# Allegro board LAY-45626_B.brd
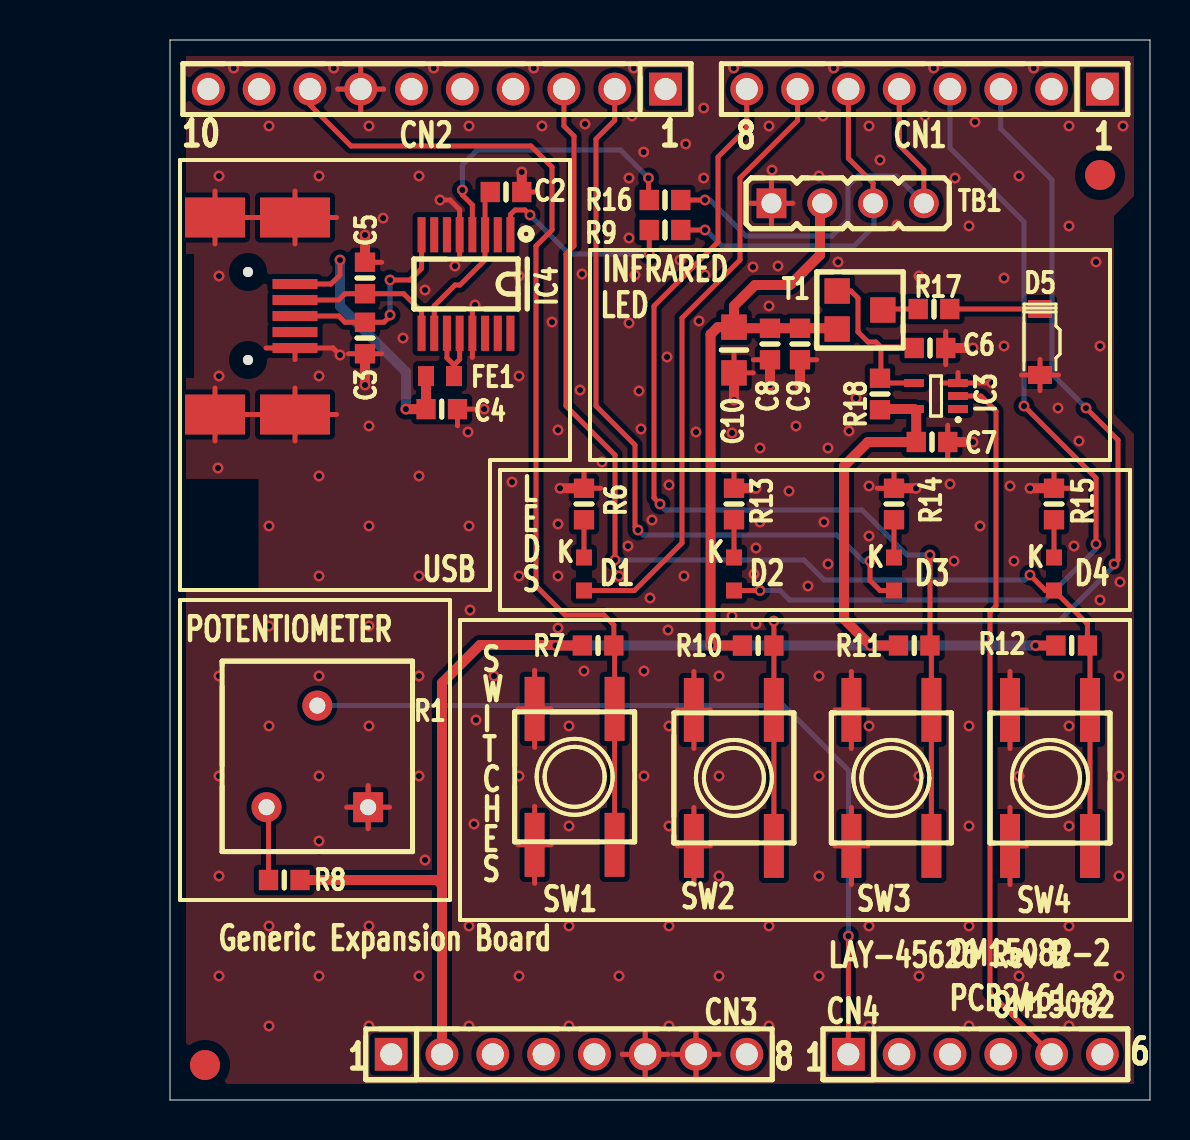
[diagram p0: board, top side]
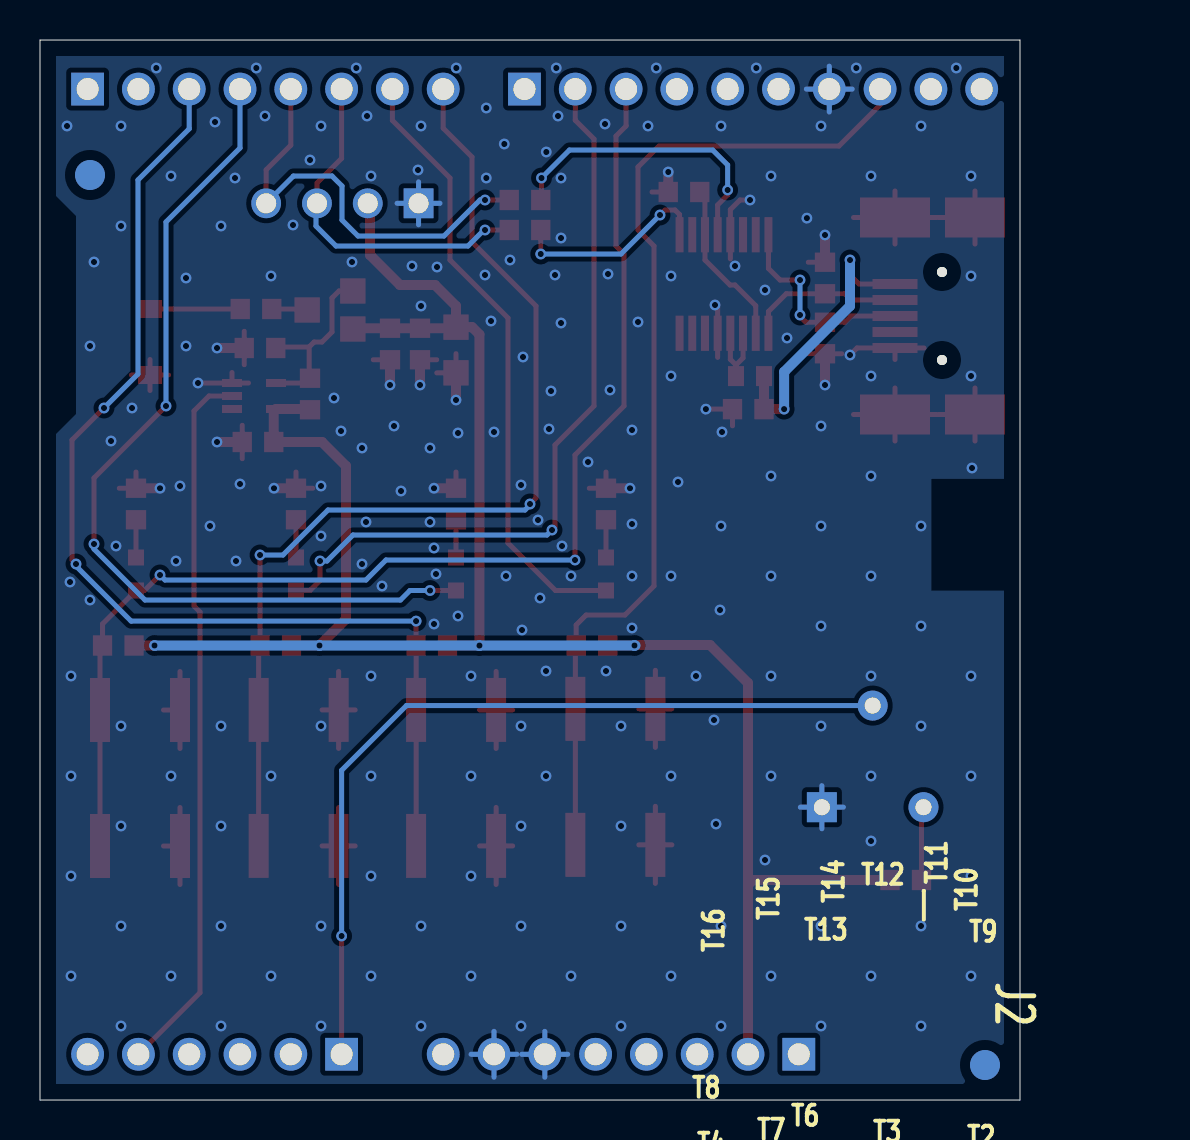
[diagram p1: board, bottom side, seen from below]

Outline 49 x 53 mm; copper layers: TOP, BOTTOM. Coordinates in mm from the lower left corner of the outline.
Outline path: 0,53 49,53 49,0 0,0 0,53

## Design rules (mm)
constraint set DEFAULT: min track width 0.15
net group ALIM: nets 3V3OUT N12889 VCC VCC3.3V VCC5V VCCUSB VIN
net group DEFAUT: nets ADC0 IR_BLASTER N01844 N09961 N10143 N10285 N10430 N15485 N15494 N16219 N16257 N23077 N262631 PIO_3 PIO_4 PIO_6 PIO_7 PIO_15 PIO_16 PIO_19 RSTN USART1_RXD USART1_TXD

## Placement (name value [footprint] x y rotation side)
1  BUBBLE-01  [BUBBLE_DIAM8]  -6.5 26.7 0 top
C2  100nF  [C0603]  16.8 45.4 0 top
C3  47pF  [C0603]  9.75 38.1 270 top
C4  10nF  [C0603]  13.59 34.54 0 top
C5  47pF  [C0603]  9.75 41.1 90 top
C6  150pF  [C0603]  38 37.6 0 top
C7  100nF  [C0603]  38.1 32.9 0 top
C8  100nF  [C0603]  30 37.8 270 top
C9  27pF  [C0603]  31.5 37.8 270 top
C10  47uF  [C0805]  28.2 37.5 270 top
CN1  -  [ESQ-108-14-L-S]  46.62 50.55 0 top
CN2  -  [ESQ-110-14-L-S]  24.78 50.55 0 top
CN3  -  [ESQ-108-14-L-S]  11.06 2.29 180 top
CN4  -  [ESQ-106-14-L-S]  33.92 2.29 180 top
D1  RED  [LED_0603_A_K]  20.7 26.3 270 top
D2  RED  [LED_0603_A_K]  28.2 26.3 270 top
D3  RED  [LED_0603_A_K]  36.2 26.3 270 top
D4  RED  [LED_0603_A_K]  44.2 26.3 270 top
D5  VSMB2948SL  [LED_VSMB2948SL]  43.5 37.9 90 top
FE1  470R  [BLM18]  13.5 36.2 0 top
IC3  74LVC1G07  [SOT353_065]  38.3 35.2 180 top
IC4  FT230XS  [JEDEC_MO137_AB_SSOP16]  14.8 40.8 180 top
J2  -  [USB_MINI-B]  0 39.2 0 top
NOREF  -  []  6.9 5.2 0 top
NOREF#2  -  []  -76.6 -194.1 0 top
NOREF#3  -  []  1 30.8 270 top
NOREF#4  -  []  16 0 90 top
NOREF#5  -  [unnamed#2]  46.5 46.25 0 top
NOREF#6  -  []  1.92 50.55 90 top
NOREF#7  -  []  0 53 0 top
NOREF#8  -  []  0 53 0 top
NOREF#9  -  []  13.15 -115.65 0 top
NOREF#10  -  [unnamed#2]  1.75 1.75 0 top
NOREF#11  -  []  0 0 90 top
NOREF#12  -  [unnamed#2]  1.75 1.75 180 bottom
NOREF#13  -  [unnamed#2]  46.5 46.25 180 bottom
R1  50K  [TRIM_63M_T607]  7.37 17.18 180 top
R6  680R  [R0603]  20.7 29.8 90 top
R7  2K20  [R0603]  21.4 22.73 0 top
R8  33K0  [R0603]  5.71 11 180 top
R9  0R  [R0603]  24.75 43.5 180 top
R10  2K20  [R0603]  29.41 22.72 0 top
R11  2K20  [R0603]  37.21 22.73 0 top
R12  2K20  [R0603]  45.09 22.73 0 top
R13  680R  [R0603]  28.2 29.8 90 top
R14  680R  [R0603]  36.2 29.8 90 top
R15  680R  [R0603]  44.2 29.8 90 top
R16  0R  [R0603]  24.75 45 180 top
R17  68R  [R0603]  38.2 39.55 0 top
R18  100K  [R0603]  35.5 35.3 90 top
SW1  EVQ-Q2P03W  [BP_EVQQ2]  20.23 16.16 270 top
SW2  EVQ-Q2P03W  [BP_EVQQ2]  28.19 16.1 270 top
SW3  EVQ-Q2P03W  [BP_EVQQ2]  36.07 16.1 270 top
SW4  EVQ-Q2P03W  [BP_EVQQ2]  44 16.1 270 top
T1  BSS84  [SOT23_1G_2S_3D]  34.5 39.5 270 top
TB1  NC  [BAR_1X4_MD]  30.07 44.83 0 top

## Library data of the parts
1 = BUBBLE: alternate symbols: (BUBBLE_DIAM4)
C2 C4 C7 C8 = CAPA: Tolerance: 10%; User Part Number: PARTNUM; alternate symbols: (0603C); tolerance: 10%
C3 C5 C6 = CAPA: Tolerance: 5%; User Part Number: PARTNUM; alternate symbols: (0603C); tolerance: 5%
C9 = CAPA: Tolerance: 5%; User Part Number: PARTNUM; tolerance: 5%
C10 = CAPA: User Part Number: PARTNUM; Tolerance: 20%; alternate symbols: (0805C); tolerance: 20%
CN1 CN3 = HEADER_8P: Tolerance: TOL; User Part Number: PAR
CN2 = HEADER_10P: Tolerance: TOL; User Part Number: PAR
CN4 = HEADER_6P: Tolerance: TOL; User Part Number: PAR
D1-D4 = LED
D5 = LED_VSMB2948G
FE1 = FERRITE_2: Tolerance: TOLERANCE; User Part Number: PARTNUM
IC3 = 74LVC1G07
IC4 = FT230XS: User Part Number: PARTNUM; Tolerance: TOLERANCE
J2 = USB_MINI-B
R1 = POT: User Part Number: PARTNUM; Tolerance: TOLERANCE
R6-R8 R10-R15 R17 = RES: User Part Number: PARTNUM; Tolerance: 1%; alternate symbols: (0603R); tolerance: 1%
R9 R16 = RES: User Part Number: PARTNUM; Tolerance: 1%; tolerance: 1%
R18 = RES: User Part Number: PARTNUM; Tolerance: 5%; tolerance: 5%
SW1-SW4 = BP_EVQQ2: User Part Number: PARTNUM; Tolerance: TOLERANCE
T1 = MOSFET_G1_S2_D3: User Part Number: PARTNUM; Tolerance: TOLERANCE
TB1 = bar_1x4_MD: Tolerance: TOLERANCE; User Part Number: PARTNUM

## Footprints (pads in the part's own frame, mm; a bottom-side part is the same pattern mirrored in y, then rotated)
BAR_1X4_MD
  rect 1.49x1.49 hole 1: 1(0,0)
  round 1.49 hole 1: 2(2.54,0) 3(5.08,0) 4(7.62,0)
BLM18
  rect 0.8x1 smd: 1(-0.7,0) 2(0.7,0)
BP_EVQQ2
  rect 3.2x1 smd: A(-3.4,-2) AP(3.4,-2) B(-3.4,2) BP(3.4,2)
BUBBLE_DIAM8
  round 0 smd: 1(0,0)
C0603
  rect 0.965x1.016 smd: 1(-0.787,0) 2(0.787,0)
C0805
  rect 1.27x1.27 smd: 1(-1.143,0) 2(1.143,0)
ESQ-106-14-L-S
  rect 1.64x1.64 hole 1.1: 1(0,0)
  round 1.64 hole 1.1: 2(-2.54,0) 3(-5.08,0) 4(-7.62,0) 5(-10.16,0) 6(-12.7,0)
ESQ-108-14-L-S
  rect 1.64x1.64 hole 1.1: 1(0,0)
  round 1.64 hole 1.1: 2(-2.54,0) 3(-5.08,0) 4(-7.62,0) 5(-10.16,0) 6(-12.7,0) 7(-15.24,0) 8(-17.78,0)
ESQ-110-14-L-S
  rect 1.64x1.64 hole 1.1: 1(0,0)
  round 1.64 hole 1.1: 2(-2.54,0) 3(-5.08,0) 4(-7.62,0) 5(-10.16,0) 6(-12.7,0) 7(-15.24,0) 8(-17.78,0) 9(-20.32,0) 10(-22.86,0)
JEDEC_MO137_AB_SSOP16
  rect 0.4x1.76 smd: 1(-2.223,-2.462) 2(-1.587,-2.462) 3(-0.953,-2.462) 4(-0.318,-2.462) 5(0.318,-2.462) 6(0.953,-2.462) 7(1.587,-2.462) 8(2.223,-2.462) 9(2.223,2.462) 10(1.587,2.462) 11(0.953,2.462) 12(0.318,2.462) 13(-0.318,2.462) 14(-0.953,2.462) 15(-1.587,2.462) 16(-2.223,2.462)
LED_0603_A_K
  rect 0.8x0.8 smd: A(0.825,0) K(-0.825,0)
LED_VSMB2948SL
  rect 0.9x1.2 smd: A(1.65,0) K(-1.65,0)
R0603
  rect 0.965x1.016 smd: 1(-0.787,0) 2(0.787,0)
SOT23_1G_2S_3D
  rect 1.27x1.27 smd: 1(-0.95,-1.143) 2(0.95,-1.143) 3(0,1.143)
SOT353_065
  rect 1x0.4 smd: 1(-1.1,0.65) 2(-1.1,0) 3(-1.1,-0.65) 4(1.1,-0.65) 5(1.1,0.65)
TRIM_63M_T607
  rect 1.5x1.5 hole 0.8: 1(-2.54,2.54)
  round 1.5 hole 0.8: 2(0,-2.54) 3(2.54,2.54)
unnamed#2
  round 1.5 smd: (0,0)
USB_MINI-B
  round 0.5 hole 0.9 unplated: (3.9,2.2) (3.9,-2.2)
  rect 2.25x0.5 smd: 1(6.25,1.6) 2(6.25,0.8) 3(6.25,0) 4(6.25,-0.8) 5(6.25,-1.6)
  rect 3.5x2 smd: A(6.25,4.925) C(6.25,-4.925)
  rect 3x2 smd: B(2.25,4.925) D(2.25,-4.925)

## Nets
3V3OUT: C2.1 IC4.3(VCCIO) IC4.10
GND: C2.2 C3.2 C4.2 C5.2 C6.2 C7.2 C8.2 C9.2 C10.2 CN2.7 CN3.6 CN3.7 D5.K IC3.3 IC4.5 IC4.13 J2.5 J2.A J2.B J2.C J2.D R1.1 R6.2 R13.2 R14.2 R15.2 SW1.A SW1.AP SW2.A SW2.AP SW3.A SW3.AP SW4.A SW4.AP TB1.1
VCC: C7.1 C8.1 C9.1 C10.1 CN3.2 IC3.5 R7.1 R8.1 R10.1 R11.1 R12.1 R18.1 T1.2(S) TB1.2
VCC3.3V: CN3.4
VCC5V: CN3.5
VCCUSB: FE1.2 IC4.11 IC4.12
VIN: CN3.8
ADC0: CN4.1 R1.2
IR_BLASTER: CN4.5 IC3.2
PIO_3: CN2.2 D3.A
PIO_4: CN2.3 D4.A R12.2 SW4.B SW4.BP
PIO_6: CN1.4 D2.A
PIO_7: CN1.8 R11.2 SW3.B SW3.BP
PIO_15: CN1.3 R10.2 SW2.B SW2.BP
PIO_16: CN1.7 D1.A
PIO_19: CN2.8 R7.2 SW1.B SW1.BP
RSTN: CN3.3
USART1_RXD: CN1.6 R9.1 TB1.3
USART1_TXD: CN1.5 R16.1 TB1.4
N01844: R1.3 R8.2
N09961: D1.K R6.1
N10143: D2.K R13.1
N10285: D3.K R14.1
N10430: D4.K R15.1
N12889: C4.1 FE1.1 J2.1(VCC)
N15485: C5.1 IC4.9 J2.2
N15494: C3.1 IC4.8 J2.3
N16219: IC4.1 R9.2
N16257: IC4.4 R16.2
N23077: C6.1 IC3.4(Y) R18.2 T1.1
N226982: R17.1 T1.3
N262631: D5.A R17.2

Pads without a net: 1 1; CN1 1 2; CN2 1 4 5 6 9 10; CN3 1; CN4 2 3 4 6; IC3 1; IC4 2 6 7 14 15 16; J2 4

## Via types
v1: diameter 0.54, hole 0.31, TOP to BOTTOM, 233 vias

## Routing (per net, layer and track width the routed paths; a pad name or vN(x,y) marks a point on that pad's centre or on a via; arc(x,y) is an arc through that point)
3V3OUT: length 8.4
  TOP w0.25: C2.1 15.75,45.14 IC4.3 15.75,43.26 15.75,42 14.5,40.75 14.25,40.75 13.21,39.71 IC4.10
GND: length 159.9
  TOP w0.25: 42,17.57 SW4.A ; SW4.A 42,21.43 ; SW4.A 42.83,19.5 ; 6.25,37.02 J2.5 ; J2.5 4.8,37.6 ; J2.5 8.15,37.6 v1(8.5,37.25) ; 21.53,30.59 R6.2 20.7,31.4 ; J2.B 2.25,45.45 ; J2.B 2.25,42.8 ; J2.B 4.08,44.13 ; D5.K 43.5,37.03 ; D5.K 43.5,35.47 ; D5.K 44.43,36.25 ; D5.K 42.57,36.25 ; SW1.A 19.06,19.56 ; SW1.A 18.23,21.48 ; SW1.A 18.23,17.63 ; SW1.A 17.41,19.56 ; SW4.AP 42.83,12.7 ; SW4.AP 42,14.63 ; SW4.AP 42,10.77 ; v1(15.25,39.75) 15.12,39.62 IC4.13 15.12,37.13 ; SW2.A 27.02,19.5 ; SW2.A 26.19,21.43 ; SW2.A 26.19,17.58 ; SW2.A 25.37,19.5 ; SW3.A 34.07,21.43 ; SW3.A 34.89,19.5 ; SW3.A 34.07,17.58 ; SW3.A 33.24,19.5 ; 29.17,37.01 C8.2 ; 38.89,32.07 C7.2 38.89,33.73 ; SW1.AP 19.06,12.76 ; SW1.AP 18.23,14.68 ; SW1.AP 18.23,10.83 ; SW1.AP 17.41,12.76 ; 25.37,12.7 SW2.AP ; SW2.AP 26.19,10.78 ; SW2.AP 27.02,12.7 ; SW2.AP 26.19,14.63 ; 29,44.83 TB1.1 ; TB1.1 31.14,44.83 ; TB1.1 30.07,43.76 ; TB1.1 30.07,45.9 ; v1(15.71,34.54) C4.2 14.37,33.71 ; C9.2 32.33,37.01 ; R13.2 28.2,31.4 ; 33.24,12.7 SW3.AP ; SW3.AP 34.07,10.78 ; SW3.AP 34.07,14.63 ; SW3.AP 34.89,12.7 ; 14.48,42.06 IC4.5 14.48,44.52 14,45 v1(13.5,45) ; J2.D 2.25,35.6 ; J2.D 4.08,34.27 ; J2.D 2.25,32.95 ; 9.91,13.56 R1.1 ; R1.1 9.91,15.72 ; R1.1 8.83,14.64 ; R1.1 10.98,14.64 ; 38.79,38.43 C6.2 38.79,36.77 ; 8.92,37.31 C3.2 10.58,37.31 ; 22.61,2.29 CN3.6 ; CN3.6 23.76,3.43 ; CN3.6 23.76,1.14 ; CN3.6 24.91,2.29 ; J2.A 8.33,44.13 ; J2.A 6.25,42.8 ; J2.A 6.25,45.45 ; J2.A 4.17,44.13 ; 45.03,30.59 R15.2 44.2,31.4 ; 35.37,30.59 R14.2 36.2,31.4 ; IC3.3 v1(41.1,35.85) ; IC3.3 39.4,36.38 ; IC3.3 38.57,35.85 ; J2.C 8.33,34.27 ; J2.C 6.25,35.6 ; J2.C 6.25,32.95 ; J2.C 4.17,34.27 ; CN2.7 10.68,50.55 ; CN2.7 9.54,51.69 ; CN2.7 8.39,50.55 ; CN2.7 9.54,49.4 ; 26.3,1.14 CN3.7 ; CN3.7 25.15,2.29 ; CN3.7 26.3,3.43 ; CN3.7 27.45,2.29 ; 29.16,36.36 C10.2 28.2,37.32 ; C2.2 18.4,45.4 ; C5.2 10.58,41.89
  TOP w0.5: C6.2 v1(40.15,37.6) ; v1(37.3,30.59) R14.2 ; v1(29.3,30.59) R13.2 ; C5.2 v1(9.75,43.25) ; v1(17.59,46.4) C2.2 ; C9.2 v1(31.5,35.75) ; C7.2 v1(40.15,32.9) ; C10.2 v1(28.2,35) ; C8.2 v1(30,35.75) ; v1(43,30.59) R15.2 ; v1(19.5,30.59) R6.2 ; C3.2 v1(9.75,35.75)
  BOTTOM w0.25: 9.54,49.4 CN2.7 ; CN2.7 8.39,50.55 ; CN2.7 9.54,51.69 ; CN2.7 10.68,50.55 ; 8.83,14.64 R1.1 ; R1.1 10.98,14.64 ; R1.1 9.91,13.56 ; R1.1 9.91,15.72 ; CN3.7 27.45,2.29 ; CN3.7 25.15,2.29 ; CN3.7 26.3,3.43 ; CN3.7 26.3,1.14 ; CN3.6 23.76,3.43 ; CN3.6 23.76,1.14 ; CN3.6 22.61,2.29 ; CN3.6 24.91,2.29 ; TB1.1 31.14,44.83 ; TB1.1 30.07,45.9 ; TB1.1 30.07,43.76 ; TB1.1 29,44.83
  vias: v1(2.4,31.6) v1(2.45,46.2) v1(2.45,41.2) v1(2.45,36.2) v1(2.45,21.2) v1(2.45,16.2) v1(2.45,11.2) v1(2.45,6.2) v1(3.19,51.6) v1(4.95,48.7) v1(4.95,28.7) v1(4.95,23.7) v1(4.95,18.7) v1(4.95,8.7) v1(4.95,3.7) v1(7.45,46.2) v1(7.45,36.2) v1(7.45,31.2) v1(7.45,26.2) v1(7.45,21.2) v1(7.45,16.2) v1(7.45,12.95) v1(7.45,6.2) v1(8.19,51.6) v1(9.95,48.7) v1(9.95,33.7) v1(9.95,28.7) v1(9.95,23.7) v1(9.95,18.7) v1(9.95,8.7) v1(9.95,3.7) v1(10.66,44.09) v1(11.65,38.1) v1(12.45,46.2) v1(12.45,31.2) v1(12.45,26.2) v1(12.45,21.2) v1(12.45,16.2) v1(12.45,6.2) v1(12.75,40.5) v1(12.75,12) v1(13.19,51.6) v1(14.25,41.7) v1(14.95,48.7) v1(14.9,33.4) v1(14.95,28.7) v1(14.95,8.7) v1(14.95,3.7) v1(15,24.5) v1(15.2,13.8) v1(15.3,19) v1(16.2,21.2) v1(17.1,30.9) v1(17.45,41.2) v1(17.45,36.2) v1(17.45,26.2) v1(17.45,16.2) v1(17.45,6.2) v1(18.19,51.6) v1(18.6,48.7) v1(19.1,38.9) v1(19.4,33.5) v1(19.4,28.8) v1(19.4,26.2) v1(19.4,23.6) v1(19.95,18.7) v1(19.95,13.7) v1(19.95,8.7) v1(19.95,3.7) v1(20.5,35.5) v1(20.6,41.3) v1(20.7,21.45) v1(20.75,48.8) v1(21.6,31.9) v1(22.45,26.2) v1(22.45,6.2) v1(22.95,46.1) v1(22.95,43.1) v1(22.95,38.85) v1(22.9,27.7) v1(23.1,49.2) v1(23.19,51.6) v1(23.25,41.25) v1(23.45,35.45) v1(23.55,33.55) v1(23.69,47.4) v1(23.7,21.45) v1(23.7,16.2) v1(24,25.1) v1(24.1,29) v1(24.85,37.15) v1(24.95,30.75) v1(24.9,23.5) v1(24.95,18.7) v1(24.95,13.7) v1(24.95,8.7) v1(24.95,3.7) v1(25.5,42) v1(25.7,26.2) v1(25.79,47.8) v1(26.3,33.4) v1(26.45,38.95) v1(26.69,49.6) v1(26.69,46.1) v1(26.75,41.25) v1(27.45,21.2) v1(27.45,16.2) v1(27.45,11.2) v1(27.45,6.2) v1(28.1,33.35) v1(28.1,24.2) v1(28.19,51.6) v1(29.15,41.65) v1(29.2,26.3) v1(29.3,27.6) v1(29.3,23.8) v1(29.5,32.6) v1(29.5,28.9) v1(29.95,48.7) v1(29.95,39.7) v1(29.95,8.7) v1(29.95,3.7) v1(30.1,46.5) v1(30.4,41.7) v1(30.95,30.45) v1(31.3,33.7) v1(31.9,25.7) v1(32.45,46.2) v1(32.45,21.2) v1(32.45,16.2) v1(32.45,11.2) v1(32.45,6.2) v1(32.65,49.2) v1(32.7,28.9) v1(32.9,32.6) v1(32.9,26.8) v1(33.19,51.6) v1(33.4,41.9) v1(33.95,33.45) v1(34.3,35.1) v1(34.95,48.7) v1(34.95,30.7) v1(34.95,28.2) v1(34.95,18.7) v1(34.95,8.7) v1(34.95,3.7) v1(35.5,47) v1(36.35,43.75) v1(37.45,41.2) v1(37.45,16.2) v1(37.45,6.2) v1(37.75,49.2) v1(38.19,51.6) v1(39,30.8) v1(39.25,46.1) v1(39.2,26.95) v1(39.95,43.7) v1(39.95,18.7) v1(39.95,13.7) v1(39.95,8.7) v1(39.95,3.7) v1(40.25,48.9) v1(40.5,28.7) v1(41.7,41.1) v1(41.7,37.7) v1(42,30.7) v1(42.2,26.95) v1(42.45,46.2) v1(42.45,16.2) v1(42.45,6.2) v1(43.19,51.6) v1(44.4,34.6) v1(44.95,48.7) v1(44.95,43.7) v1(44.95,18.7) v1(44.95,13.7) v1(44.95,8.7) v1(44.95,3.7) v1(45.2,27.7) v1(45.45,32.95) v1(46.3,41.9) v1(46.5,37.7) v1(46.5,25) v1(47.5,25.9) v1(47.45,21.2) v1(47.45,16.2) v1(47.45,11.2) v1(47.45,6.2) v1(47.65,48.7)
VCC: length 109.8
  TOP w0.5: R12.1 v1(43.27,22.73) ; T1.2 33.32,38.59 C9.1 C8.1 28.26,38.59 C10.1 ; R8.1 13.35,11 13.6,10.75 ; C10.1 28.2,39.7 29.25,40.75 31,40.75 32.5,42.25 32.5,44.72 TB1.2 ; C10.1 27.39,38.64 27.03,38.28 v1(27.03,22.72) R10.1 ; 13.6,10.75 CN3.2 ; 13.6,10.75 13.6,20.85 15.5,22.75 19.25,22.75 v1(19.27,22.73) R7.1 ; R11.1 v1(35.02,22.73) 33.7,24.05 33.7,31.7 34.9,32.9 C7.1 37.31,34.44 IC3.5 35.54,34.55 R18.1
  BOTTOM w0.5: v1(43.27,22.73) v1(35.02,22.73) 27.03,22.73 v1(27.03,22.72) 19.28,22.72 v1(19.27,22.73) 19.23,22.73
VCCUSB: length 4
  TOP w0.25: IC4.11 13.85,37.1 14.2,36.75 ; IC4.12 14.48,37.03 14.2,36.75 ; 14.2,36.75 FE1.2
ADC0: length 42.1
  TOP w0.25: R1.2 7.4,19.75 ; CN4.1 v1(33.92,8.2)
  BOTTOM w0.25: R1.2 30.68,19.72 33.92,16.48 v1(33.92,8.2)
IR_BLASTER: length 35.8
  TOP w0.25: IC3.2 40.55,35.2 41.3,34.45 41.3,24.7 41,24.4 41,5.37 CN4.5
PIO_3: length 37.9
  TOP w0.25: v1(23.4,28.5) 23.25,28.65 23.25,32.75 21.3,34.7 21.3,48.05 22.24,48.99 CN2.2 ; v1(35,26.95) 35,25.98 35.5,25.48 D3.A
  BOTTOM w0.25: v1(35,26.95) 34.65,26.95 33.35,28.25 23.65,28.25 v1(23.4,28.5)
PIO_4: length 61.2
  TOP w0.25: CN2.3 19.7,48.7 20.2,48.2 20.2,42.7 19.8,42.3 19.8,34.7 22.25,32.25 v1(22.25,27) ; SW4.BP SW4.B 46,22.6 R12.2 45.87,23.8 D4.A 43.77,25.48 v1(43,26.25)
  BOTTOM w0.25: v1(43,26.25) 42.75,26 32.7,26 31.7,27 v1(22.25,27)
PIO_6: length 45.4
  TOP w0.25: v1(42.7,34.7) 46.3,31.1 v1(46.3,27.8) ; D2.A v1(29.5,25.48)
  BOTTOM w0.25: v1(46.3,27.8) 46.3,27.55 43.75,25 30.98,25 30.5,25.48 v1(29.5,25.48) ; v1(42.7,34.7) 42.7,43.9 39,47.6 CN1.4
PIO_7: length 52
  TOP w0.25: CN1.8 28.84,48.59 27.4,47.15 27.4,42.9 24.2,39.7 24.2,30.1 v1(24.5,29.8) ; SW3.BP SW3.B 38.07,22.66 R11.2 v1(38,27.25)
  BOTTOM w0.25: v1(24.5,29.8) 24.5,29.75 24.75,29.5 34.6,29.5 36.85,27.25 v1(38,27.25)
PIO_15: length 55.7
  TOP w0.25: v1(30.2,23.95) R10.2 30.19,22.72 SW2.B SW2.BP ; v1(47.2,26.8) 47.4,27 47.4,33 v1(45.8,34.6)
  BOTTOM w0.25: v1(45.8,34.6) 44.1,36.3 44.1,46 41.54,48.56 CN1.3 ; v1(47.2,26.8) 47.2,26.7 44.45,23.95 v1(30.2,23.95)
PIO_16: length 31
  TOP w0.25: CN1.7 31.38,48.98 28.5,46.1 28.5,42 25.6,39.1 25.6,27.85 23.23,25.48 D1.A
PIO_19: length 51.2
  TOP w0.25: CN2.8 7,49.75 9.05,47.7 18.05,47.7 19.1,46.65 19.1,43.5 18.3,42.7 18.3,25.7 19.75,24.25 21.69,24.25 22.19,23.75 R7.2 22.23,22.68 SW1.B SW1.BP
USART1_RXD: length 17.8
  TOP w0.25: TB1.3 35.15,45.85 33.92,47.08 CN1.6 ; R9.1 v1(26.75,43.5)
  BOTTOM w0.25: TB1.3 35.2,44.79 35.2,43.7 34.2,42.7 27.6,42.7 26.8,43.5 v1(26.75,43.5)
USART1_TXD: length 21.9
  TOP w0.25: R16.1 v1(26.75,45) ; CN1.5 36.46,47.74 37.69,46.51 TB1.4
  BOTTOM w0.25: v1(26.75,45) 27,45 28.8,43.2 33.1,43.2 33.9,44 33.9,45.7 34.4,46.2 36.33,46.2 TB1.4
N01844: length 3.7
  TOP w0.25: R8.2 4.93,14.54 R1.3
N09961: length 1.9
  TOP w0.25: D1.K R6.1
N10143: length 1.9
  TOP w0.25: D2.K R13.1
N10285: length 1.9
  TOP w0.25: D3.K R14.1
N10430: length 1.9
  TOP w0.25: D4.K R15.1
N12889: length 14.7
  TOP w0.25: 12.75,36.25 FE1.1 ; v1(8.5,42) 8.5,41.25 8.05,40.8 J2.1
  TOP w0.5: v1(11.79,34.54) C4.1 FE1.1
  BOTTOM w0.5: v1(8.5,42) 8.5,39.7 11.79,36.41 v1(11.79,34.54)
N15485: length 7.9
  TOP w0.25: IC4.9 12.58,39.42 11.69,40.31 C5.1 8.75,40.31 8.44,40 J2.2
N15494: length 10.3
  TOP w0.25: v1(11,41) 12,41 12.58,41.58 IC4.8 ; J2.3 8.44,39.2 8.75,38.89 C3.1 10.7,38.89 11,39.19 v1(11,39.25)
  BOTTOM w0.25: v1(11,41) v1(11,39.25)
N16219: length 10.2
  TOP w0.25: v1(18,44.25) 17.75,44.5 17.25,44.5 17.02,44.27 IC4.1 ; R9.2 v1(23.96,42.3)
  BOTTOM w0.25: v1(18,44.25) 19.95,42.3 v1(23.96,42.3)
N16257: length 15
  TOP w0.25: v1(14.62,45.5) 14.62,45.25 15.12,44.75 IC4.4 ; v1(23.93,46.1) 23.93,45.04 R16.2
  BOTTOM w0.25: v1(23.93,46.1) 22.53,47.5 15.37,47.5 14.62,46.75 v1(14.62,45.5)
N23077: length 9.4
  TOP w0.25: 35.54,37.65 37.16,37.65 C6.1 ; 35.54,37.65 35.29,37.9 34.9,37.9 34.4,38.4 34.4,40.1 34.05,40.45 T1.1 ; 35.54,37.65 35.54,36.13 R18.2 35.74,35.85 IC3.4
N226982: length 1.8
  TOP w0.25: R17.1 35.69,39.55 T1.3
N262631: length 4.5
  TOP w0.25: D5.A R17.2

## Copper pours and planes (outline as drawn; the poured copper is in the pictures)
GND on TOP, BOTTOM: 0.8,52.2 48.2,52.2 48.2,45.2 47.2,44.2 47.2,34.3 48.2,33.3 48.2,0.8 0.8,0.8

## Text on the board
Ref Des/Silkscreen Bottom: T9 | T2 | T3 | T12 | T13 | T6 | T7 | T4 | T5 | T8 | T10 | T11 | T14 | T15 | T16 | J1 | J2
Ref Des/Silkscreen Top: POTENTIOMETER | Generic Expansion Board | USB | S | W | I | T | C | H | E | L | D | LED | INFRARED | LAY-45626 Rev B | OM15082-2 | PCB2461-2 | OM15082
BODY_CENTER: TITRE | TITLE | . | No EVOL | DESSINE/DRAWN | ASCO-SR | REV. | Nbr/Qty | DATE | 08-Nov-19 | EVOLUTION/CHANGE | M.BAUDRY | VERIFIE/CHECKED | NUMERO DOCUMENT/DOCUMENT NUMBER | DESS./DRAWN | APPROUVE/APPROVED | ..-..-.... | VERIF./CHECKED | PAGE | Austin, TX 78735-8598 | 6501 William Cannon Drive West | SEMICONDUCTORS | 7 | OM15082 - GENERIC EXPANSION BOARD | / | LAY-45626 | B
DEVICE_TYPE_TOP: 4 | LAYER1 - TOP LAYER
DISPLAY_TOP: 5 | LAYER2 - BOTTOM LAYER
COMPVAL_TYPE_TOP: 4 | LAYER 2 | 311
TOLERANCE_TOP: 4 | LAYER 3 | 311
User.18: 2 | SILKSCREEN TOP
User.19: 6 | SOLDERMASK BOTTTOM
User.20: 4 | PASTEMASK BOT | 435
User.22: 1 | PASTEMASK TOP
User.24: 3 | SOLDERMASK TOP
User.25: 7 | OUTLINE
User.45: FIGURE | DIAMETRE / HOLESIZE | 0,30 mm (PERCE) | 0,80 mm +0,10 -0,05 | 1,00 mm +0,10 -0,05 | 1,10 mm +0,10 -0,05 | 0,90 mm +0,10 -0,10 | LEGENDE DE PERCAGE / DRILL LEGEND | ALL UNITS ARE IN MILLIMETERS | PLATED | NON-PLATED | Qte / Qty | 233 | 3 | 4 | 32 | 2 | <VIA | 30 | . | 17.5um | COLOR | BLUE | Ep | Rainurage/Breakaway rail | 1.6mm ; | e=0.4mm 0.10mm | e | File. | 1/1 | 3/1 | GENERIC EXPANSION BOARD | ASSEMBLY DRAWING TOP - OM15082 | 1 | LAY-45626 | A
